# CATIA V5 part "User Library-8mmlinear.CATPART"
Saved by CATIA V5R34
Part number: D52C692C-E2C8-410B-91D2-951A21E0B79C
Revision: ANY
Definition: UNKNOWN
Nomenclature: D52C692C-E2C8-410B-91D2-951A21E0B79C
Source: Unknown
Bounding box of the stored display mesh (mm): x -6 to 6, y -6 to 6, z 0 to 18.5
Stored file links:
  C:\Users\Apolinar\Desktop\cnc\User Library-8mmlinear.CATPART
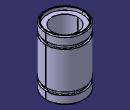
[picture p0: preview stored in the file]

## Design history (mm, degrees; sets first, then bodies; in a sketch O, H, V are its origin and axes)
Set1
  Sketch1 on face of Solid1, origin (0, 0, 17.5), H (1, 0, 0), V (0, 1, 0)
    circle A1 centre (0, 0) radius 4
    radius A1 = 4
Body1 "Congé1" (main body)
  Solid1: solid without history
  Pocket1: profile Sketch1, direction (0, 0, -1), through (limit type 6)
